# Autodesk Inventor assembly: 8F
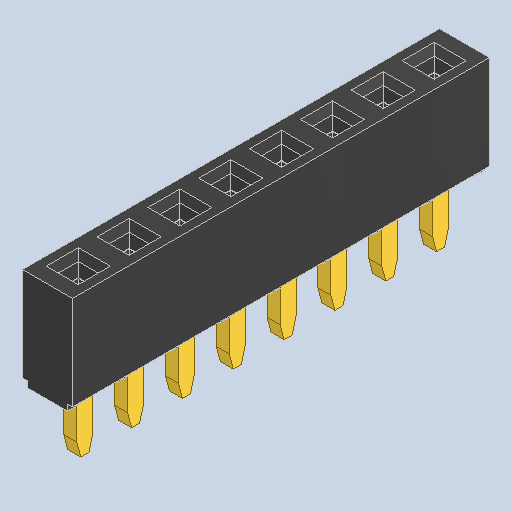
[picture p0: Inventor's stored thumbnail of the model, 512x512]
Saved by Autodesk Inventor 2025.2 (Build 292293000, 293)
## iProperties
Created: 2025-04
Part Number: 8F
Description: PART--DESC
Document SubType Name: Assembly
Designer: BennF
Author: BennF
Revision Number: NONE
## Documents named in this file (3)
- C:\Users\BennF\Nextcloud\Benutzer\CNC JarBeRi\existing parts\Electronics\RepRap A4988 Shied (USE WITHOUT ARDUINO)\reprap-a4988-1.snapshot.1\RepRap\RepRap\8F_2.iam
- C:\Users\BennF\Nextcloud\Benutzer\CNC JarBeRi\existing parts\Electronics\RepRap A4988 Shied (USE WITHOUT ARDUINO)\reprap-a4988-1.snapshot.1\RepRap\RepRap\8F Geometry.ipt
- C:\Users\BennF\Nextcloud\Benutzer\CNC JarBeRi\existing parts\Electronics\RepRap A4988 Shied (USE WITHOUT ARDUINO)\reprap-a4988-1.snapshot.1\RepRap\RepRap\Pin3.ipt
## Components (2 placed, 2 different names)
1. 8F Geometry
2. Pin3
